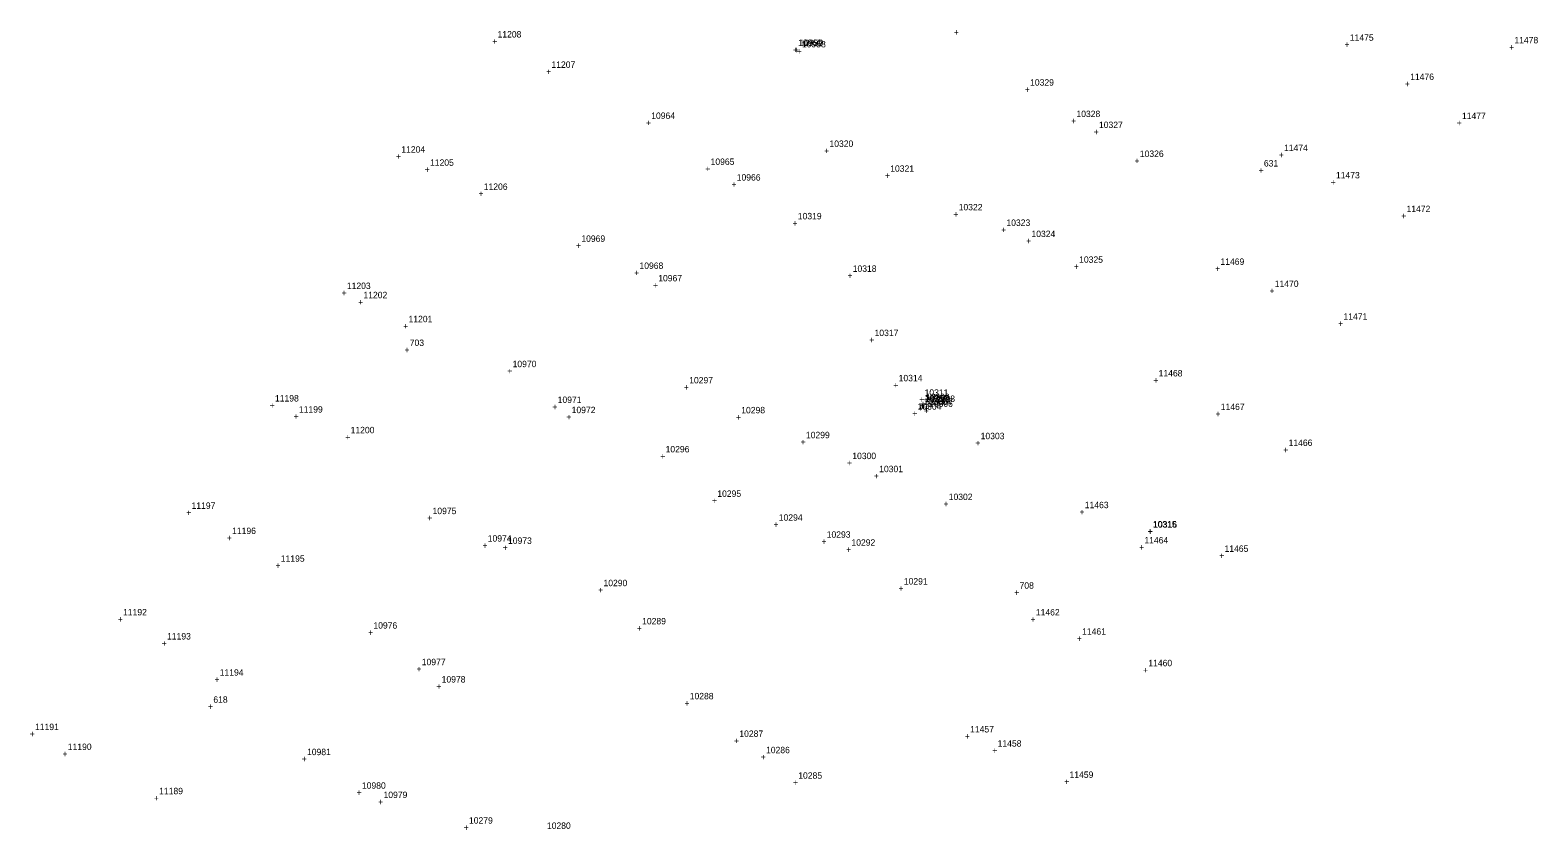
# Model space of a CAD drawing. Extents: x 1160051 to 1162814, y 614604 to 619560.
# Drawn here: x 1160652 to 1161240, y 616463 to 616775 of the extents above; entities that cross this region are included whole.
import ezdxf

# ---------------------------------------------------------------- set-up
doc = ezdxf.new("R2010")
doc.units = 0
for name, color, linetype in [('S_Control_Temp_Traverse', 7, 'Continuous'), ('S_Control_Traverse_Point', 7, 'Continuous'), ('S_Drainage_Culvert_Top', 7, 'Continuous'), ('S_Drainage_Invert', 7, 'Continuous'), ('S_Ground_Elevation', 7, 'Continuous')]:
    doc.layers.add(name, color=color, linetype=linetype)

msp = doc.modelspace()

# ---------------------------------------------------------------- texts
at = {"layer": 'S_Control_Temp_Traverse'}
for s, p in [('+', (1161131.19, 616718.85)), ('631', (1161133.26, 616721.6)), ('618', (1160723.32, 616512.26)), ('+', (1160721.25, 616509.51))]:
    msp.add_text(s, height=2.5, dxfattribs=at).set_placement(p)
at = {"layer": 'S_Control_Traverse_Point'}
for s, p in [('+', (1160797.9, 616648.79)), ('+', (1160797.9, 616648.79)), ('703', (1160799.96, 616651.54)), ('703', (1160799.96, 616651.54)), ('+', (1161035.85, 616554.05)), ('+', (1161035.85, 616554.05)), ('+', (1161035.85, 616554.05)), ('+', (1161035.85, 616554.05)), ('+', (1161035.85, 616554.05)), ('+', (1161035.85, 616554.05)), ('+', (1161035.85, 616554.05)), ('+', (1161035.85, 616554.05)), ('+', (1161035.85, 616554.05)), ('+', (1161035.85, 616554.05)), ('+', (1161035.85, 616554.05)), ('+', (1161035.85, 616554.05)), ('708', (1161037.92, 616556.8)), ('708', (1161037.92, 616556.8)), ('708', (1161037.92, 616556.8)), ('708', (1161037.92, 616556.8)), ('708', (1161037.92, 616556.8)), ('708', (1161037.92, 616556.8)), ('708', (1161037.92, 616556.8)), ('708', (1161037.92, 616556.8)), ('708', (1161037.92, 616556.8)), ('708', (1161037.92, 616556.8)), ('708', (1161037.92, 616556.8)), ('708', (1161037.92, 616556.8))]:
    msp.add_text(s, height=2.5, dxfattribs=at).set_placement(p)
at = {"layer": 'S_Drainage_Culvert_Top'}
for s, p in [('+', (1160949.45, 616765.93)), ('10960', (1160951.51, 616768.68)), ('+', (1160999.57, 616626.45)), ('10313', (1161001.64, 616629.2)), ('+', (1161087.85, 616577.96)), ('10315', (1161089.91, 616580.71))]:
    msp.add_text(s, height=2.5, dxfattribs=at).set_placement(p)
at = {"layer": 'S_Drainage_Invert'}
for s, p in [('+', (1160949.97, 616765.9)), ('10959', (1160952.03, 616768.65)), ('10312', (1161000.92, 616629.83)), ('+', (1160998.86, 616627.08)), ('+', (1161088.01, 616577.84)), ('10316', (1161090.07, 616580.59))]:
    msp.add_text(s, height=2.5, dxfattribs=at).set_placement(p)
at = {"layer": 'S_Ground_Elevation'}
for s, p in [('11208', (1160834.22, 616771.96)), ('+', (1161012.26, 616772.74)), ('+', (1160832.16, 616769.21)), ('10958', (1160953, 616768.1)), ('+', (1161164.73, 616767.92)), ('11475', (1161166.79, 616770.67)), ('+', (1161228.95, 616766.94)), ('11478', (1161231.01, 616769.69)), ('11207', (1160855.25, 616760.12)), ('+', (1160950.93, 616765.35)), ('+', (1160853.19, 616757.37)), ('10329', (1161042.03, 616753.18)), ('11476', (1161190.35, 616755.39)), ('+', (1161039.97, 616750.43)), ('+', (1161188.29, 616752.64)), ('+', (1160892.12, 616737.44)), ('10964', (1160894.18, 616740.19)), ('+', (1161058.05, 616738.15)), ('10328', (1161060.11, 616740.9)), ('10327', (1161068.91, 616736.62)), ('+', (1161208.49, 616737.37)), ('11477', (1161210.55, 616740.12)), ('+', (1161066.85, 616733.87)), ('+', (1160794.61, 616724.29)), ('11204', (1160796.67, 616727.04)), ('+', (1160961.68, 616726.51)), ('10320', (1160963.74, 616729.26)), ('10326', (1161084.85, 616725.34)), ('+', (1161139.07, 616724.91)), ('11474', (1161141.13, 616727.66)), ('+', (1160805.81, 616719.12)), ('11205', (1160807.87, 616721.87)), ('+', (1160915.29, 616719.48)), ('10965', (1160917.35, 616722.23)), ('10321', (1160987.45, 616719.53)), ('+', (1161082.79, 616722.59)), ('11206', (1160828.84, 616712.48)), ('+', (1160925.49, 616713.35)), ('10966', (1160927.55, 616716.1)), ('+', (1160985.39, 616716.78)), ('+', (1161159.31, 616714.22)), ('11473', (1161161.37, 616716.97)), ('+', (1160826.78, 616709.73)), ('10319', (1160951.38, 616700.99)), ('+', (1161012.1, 616701.74)), ('10322', (1161014.16, 616704.49)), ('+', (1161186.86, 616701.07)), ('11472', (1161188.92, 616703.82)), ('+', (1160949.32, 616698.24)), ('+', (1161030.73, 616695.67)), ('10323', (1161032.79, 616698.42)), ('+', (1160864.85, 616689.45)), ('10969', (1160866.92, 616692.2)), ('+', (1161040.5, 616691.31)), ('10324', (1161042.56, 616694.06)), ('10325', (1161061.17, 616684)), ('11469', (1161116.31, 616683.21)), ('+', (1160887.54, 616678.88)), ('10968', (1160889.6, 616681.63)), ('10967', (1160896.93, 616676.76)), ('+', (1160970.75, 616677.73)), ('10318', (1160972.81, 616680.48)), ('+', (1161059.11, 616681.25)), ('+', (1161114.24, 616680.46)), ('11203', (1160775.42, 616673.79)), ('+', (1160894.87, 616674.01)), ('+', (1161135.43, 616671.84)), ('11470', (1161137.5, 616674.59)), ('+', (1160773.36, 616671.04)), ('+', (1160779.83, 616667.43)), ('11202', (1160781.89, 616670.18)), ('11201', (1160799.48, 616660.81)), ('11471', (1161164.31, 616661.79)), ('+', (1160797.42, 616658.06)), ('10317', (1160981.34, 616655.4)), ('+', (1161162.25, 616659.04)), ('+', (1160979.28, 616652.65)), ('10970', (1160840.09, 616643.26)), ('+', (1160838.03, 616640.51)), ('10297', (1160909, 616636.93)), ('10314', (1160990.73, 616637.76)), ('+', (1161090.13, 616636.89)), ('11468', (1161092.19, 616639.64)), ('11198', (1160747.36, 616629.86)), ('+', (1160906.94, 616634.18)), ('+', (1160988.67, 616635.01)), ('10311', (1161000.86, 616632.1)), ('10310', (1161001.11, 616629.73)), ('10309', (1161001.32, 616630.43)), ('10308', (1161003.44, 616629.69)), ('+', (1160745.3, 616627.11)), ('11199', (1160756.71, 616625.53)), ('+', (1160855.62, 616626.55)), ('10971', (1160857.68, 616629.3)), ('10972', (1160863.14, 616625.31)), ('10298', (1160929.31, 616625.26)), ('10304', (1160998.13, 616626.65)), ('+', (1160998.42, 616625.8)), ('+', (1160998.8, 616629.36)), ('+', (1160999.05, 616626.98)), ('+', (1160999.26, 616627.68)), ('+', (1161000.54, 616625.01)), ('10305', (1161000.48, 616628.55)), ('+', (1161000.71, 616625.92)), ('+', (1161001.38, 616626.94)), ('10306', (1161002.6, 616627.76)), ('10307', (1161002.77, 616628.66)), ('11467', (1161116.44, 616626.55)), ('+', (1160754.65, 616622.78)), ('+', (1160861.08, 616622.56)), ('+', (1160927.25, 616622.51)), ('+', (1160996.07, 616623.9)), ('+', (1161114.37, 616623.8)), ('+', (1160774.82, 616614.72)), ('11200', (1160776.88, 616617.47)), ('+', (1160952.49, 616612.78)), ('10299', (1160954.55, 616615.53)), ('10303', (1161022.73, 616615.15)), ('11466', (1161142.9, 616612.51)), ('+', (1160897.74, 616607.24)), ('10296', (1160899.8, 616609.99)), ('10300', (1160972.65, 616607.37)), ('+', (1161020.67, 616612.4)), ('+', (1161140.83, 616609.76)), ('+', (1160970.59, 616604.62)), ('10301', (1160983.13, 616602.27)), ('+', (1160981.07, 616599.52)), ('+', (1160917.91, 616589.89)), ('10295', (1160919.97, 616592.64)), ('10302', (1161010.28, 616591.39)), ('+', (1160712.76, 616585.21)), ('11197', (1160714.82, 616587.96)), ('+', (1160806.8, 616583.14)), ('10975', (1160808.86, 616585.89)), ('10294', (1160943.97, 616583.32)), ('+', (1161008.21, 616588.64)), ('+', (1161061.3, 616585.47)), ('11463', (1161063.36, 616588.22)), ('11196', (1160730.65, 616578.14)), ('+', (1160941.91, 616580.57)), ('10293', (1160962.66, 616576.68)), ('+', (1160728.59, 616575.39)), ('+', (1160828.34, 616572.41)), ('10974', (1160830.4, 616575.16)), ('+', (1160836.24, 616571.54)), ('10973', (1160838.3, 616574.29)), ('+', (1160960.6, 616573.93)), ('10292', (1160972.31, 616573.57)), ('+', (1161084.56, 616571.7)), ('11464', (1161086.62, 616574.45)), ('11465', (1161117.9, 616571.17)), ('11195', (1160749.64, 616567.29)), ('+', (1160970.25, 616570.82)), ('+', (1161115.84, 616568.42)), ('+', (1160747.58, 616564.54)), ('+', (1160873.5, 616555.01)), ('10290', (1160875.56, 616557.76)), ('+', (1160990.69, 616555.66)), ('10291', (1160992.76, 616558.41)), ('+', (1160686.02, 616543.61)), ('11192', (1160688.08, 616546.36)), ('10289', (1160890.63, 616542.87)), ('+', (1161042.2, 616543.57)), ('11462', (1161044.27, 616546.32)), ('11193', (1160705.25, 616536.95)), ('+', (1160783.72, 616538.44)), ('10976', (1160785.78, 616541.19)), ('+', (1160888.57, 616540.12)), ('+', (1161060.27, 616536.1)), ('11461', (1161062.33, 616538.85)), ('+', (1160703.18, 616534.2)), ('+', (1160802.59, 616524.17)), ('10977', (1160804.65, 616526.92)), ('11460', (1161088.16, 616526.52)), ('+', (1160723.74, 616520.1)), ('11194', (1160725.8, 616522.85)), ('10978', (1160812.41, 616520.15)), ('+', (1161086.1, 616523.77)), ('+', (1160810.35, 616517.4)), ('10288', (1160909.21, 616513.61)), ('+', (1160907.15, 616510.86)), ('11191', (1160653.73, 616501.58)), ('11457', (1161018.63, 616500.66)), ('+', (1160651.67, 616498.83)), ('+', (1160926.51, 616496.18)), ('10287', (1160928.57, 616498.93)), ('+', (1161016.57, 616497.91)), ('11458', (1161029.36, 616495.13)), ('+', (1160664.46, 616491.07)), ('11190', (1160666.52, 616493.82)), ('+', (1160757.81, 616489.05)), ('10981', (1160759.87, 616491.8)), ('+', (1160936.92, 616489.81)), ('10286', (1160938.98, 616492.56)), ('+', (1161027.3, 616492.38)), ('10285', (1160951.57, 616482.6)), ('11459', (1161057.42, 616482.93)), ('10980', (1160781.29, 616478.68)), ('+', (1160949.51, 616479.85)), ('+', (1161055.36, 616480.18)), ('+', (1160700.11, 616473.8)), ('11189', (1160702.17, 616476.55)), ('+', (1160779.22, 616475.93)), ('+', (1160787.66, 616472.32)), ('10979', (1160789.73, 616475.07)), ('10279', (1160823.07, 616465.07)), ('+', (1160821.01, 616462.32)), ('10280', (1160853.48, 616463.02))]:
    msp.add_text(s, height=2.5, dxfattribs=at).set_placement(p)

doc.saveas('drawing.dxf')
